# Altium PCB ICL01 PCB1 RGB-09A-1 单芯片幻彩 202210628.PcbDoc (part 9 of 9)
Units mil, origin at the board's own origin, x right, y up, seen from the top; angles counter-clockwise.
Board outline 17436.43 x 6581.89 mil, 2 copper layers (Top Layer, Bottom Layer), stack 65.792 mil thick; 425 components, 516 nets, 1625 pads, 2772 vias.
Unrouted connection lines stored in the file: 1.
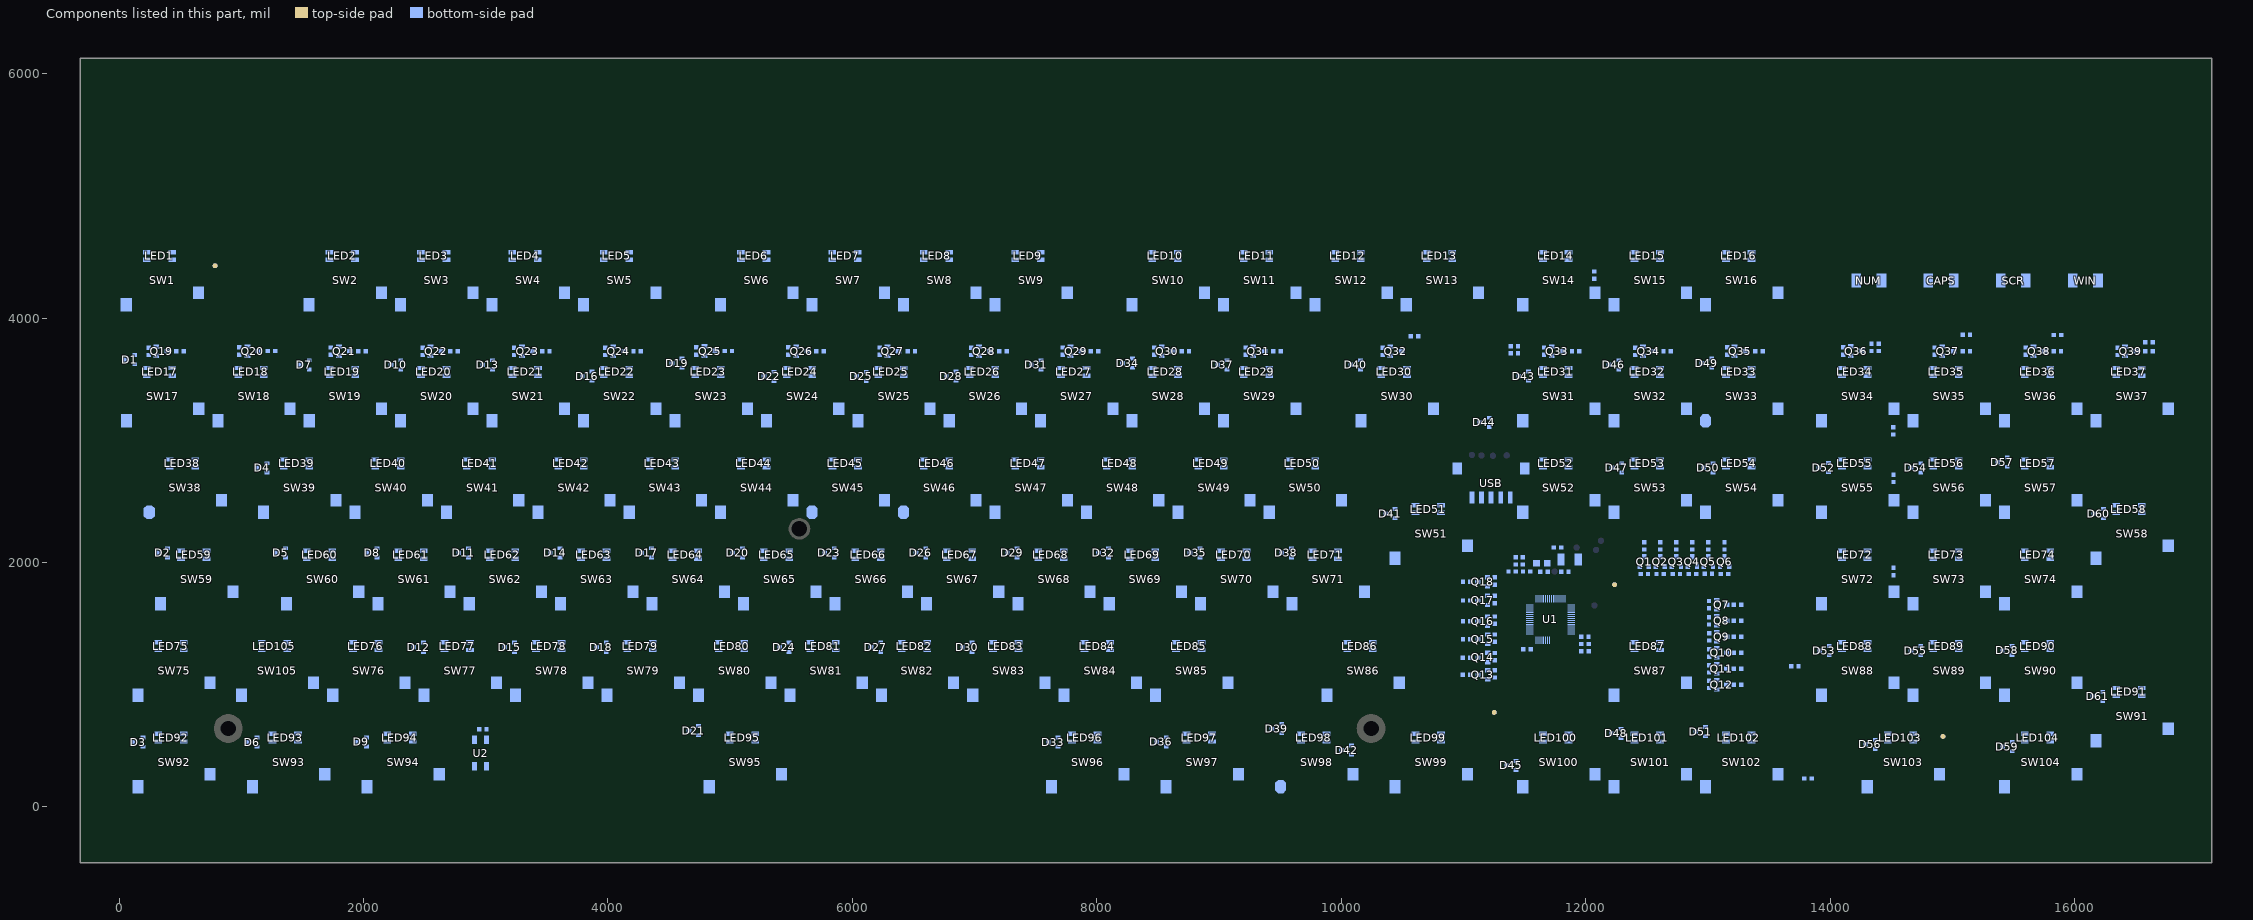
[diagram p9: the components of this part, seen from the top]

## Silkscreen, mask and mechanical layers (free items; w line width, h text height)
Top Overlay:
  rectangle: 3025.66,236.22 3238.26,496.06
  rectangle: 6962.67,236.22 7175.27,496.06
  rectangle: 9850.59,3212.02 10118.31,3530.13
  rectangle: 10795.47,3212.02 11063.19,3530.13
  rectangle: 13951.28,197.45 14219,515.56
  rectangle: 14896.16,197.45 15163.88,515.56
  rectangle: 9564.97,961.87 9832.69,1279.98
  rectangle: 10515.82,964.96 10777.57,1279.98
  region: 10881.14,1631.9 10881.14,1899.61 10563.03,1899.61 10563.03,1631.9
  region: 10881.14,2576.78 10881.14,2844.49 10563.03,2844.49 10563.03,2576.78
  rectangle: 16281.51,138.29 16599.62,406
  rectangle: 16281.51,1083.17 16599.62,1350.89
  rectangle: 16280.84,1636.32 16598.95,1904.04
  rectangle: 16280.84,2581.2 16598.95,2848.92
  lines w0.5: 149.68,850.4 ccw(c161.49,850.4) 161.49,838.59 689.05,838.59 ccw(c689.05,850.4) 700.86,850.4 700.86,1377.96 ccw(c689.05,1377.96) 689.05,1389.77 161.49,1389.77 ccw(c161.49,1377.96) 149.68,1377.96 149.68,850.4 ; 996.14,850.4 ccw(c1007.95,850.4) 1007.95,838.59 1535.51,838.59 ccw(c1535.51,850.4) 1547.32,850.4 1547.32,1377.96 ccw(c1535.51,1377.96) 1535.51,1389.77 1007.95,1389.77 ccw(c1007.95,1377.96) 996.14,1377.96 996.14,850.4
  text "ICL01 PCB1 V10" at 3399.1,360.91 h78.74
  text "20210628" at 3407.15,204.49 h47.24
Bottom Overlay:
  drawing of 720 lines, arcs and shapes, not listed
  text "GND" at 11310.66,2956.81 h39.37 r180
  text "VCC" at 11047.6,2915.81 h39.37 r270
  text "D+" at 11129.07,2909.42 h39.37 r270
  text "D-" at 11219.6,2908.35 h39.37 r270
Mechanical 1:
  drawing of 178 lines, arcs and shapes, not listed
Mechanical 2:
  drawing of 332 lines, arcs and shapes, not listed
